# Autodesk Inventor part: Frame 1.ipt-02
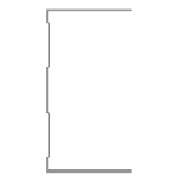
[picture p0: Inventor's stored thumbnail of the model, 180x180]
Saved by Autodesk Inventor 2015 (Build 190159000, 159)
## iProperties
IsCustomPart: 1
Created: 2015-04
Part Number: Frame 1.ipt-02
Material: Aluminum 6061
Description: Kévin Novo
Document SubType Name: Modeling
Standard: Kevin
Designer: suporte
Standards Organization: Kevin
Language: en-US
Size Designation: (Unnamed 2)
Categories: <MemberInstance><Categories><Category DisplayName="Structural Shapes" InternalName="089c4875-fa83-4c05-b084-43b9cc11f5ed" Mnemonic="GRDR"><CategoryParameter Dis
Density: 2.7 g/cm^3
Appearance: Aluminum - Flat
_CCFamilyMember: 2
_CCFamilyDisplayName: Kévin - Kévin Novo
_FrameMemberDoc: Frame Member File
_Version: 15.0.0
_GetPNFromCC: 1
G_W: 50,000 mm
G_H: 75,000 mm
G_L: 2100,000 mm
Author: suporte
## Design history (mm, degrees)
node "Start Plane"
node "End Plane"
sketch "Sketch"
  geometry: L1 (24.7, 37.5)-(24.7, 36.9); L2 (24.7, 36.9)-(-24.7, 36.9); L3 (-24.7, -36.9)-(24.7, -36.9); L4 (24.7, -36.9)-(24.7, -37.5); L5 (24.7, -37.5)-(-25.3, -37.5); L6 (-25.3, 37.5)-(24.7, 37.5); L7 (-24.7, 36.9)-(-24.7, 31.9); L8 (-24.7, 31.9)-(-23.3, 30.5); L9 (-23.3, 30.5)-(-23.3, 10.934); L10 (-23.3, 10.934)-(-24.7, 9.534); L11 (-24.7, 9.534)-(-24.7, -9.534); L12 (-24.7, -9.534)-(-23.3, -10.934); L13 (-23.3, -10.934)-(-23.3, -30.5); L14 (-23.3, -30.5)-(-24.7, -31.9); L15 (-24.7, -31.9)-(-24.7, -36.9); L16 (-25.3, -37.5)-(-25.3, -31.651); L17 (-25.3, -31.651)-(-23.9, -30.251); L18 (-23.9, -30.251)-(-23.9, -11.183); L19 (-23.9, -11.183)-(-25.3, -9.783); L20 (-25.3, -9.783)-(-25.3, 9.783); L21 (-25.3, 9.783)-(-23.9, 11.183); L22 (-23.9, 11.183)-(-23.9, 30.251); L23 (-23.9, 30.251)-(-25.3, 31.651); L24 (-25.3, 31.651)-(-25.3, 37.5); L25 (-25.3, 0)-(30.37, 0); 3 further points
  constraints: 50 end point, 10 point on line, 9 parallel, 5 perpendicular, 4 equal length, 3 midpoint, 3 vertical, 2 vertical alignment, 1 collinear, 1 horizontal, 1 horizontal alignment
  dimensions: "d3" = 0.6 distance of L1.start L1.end (= d6); "d5" = 75 distance between parallel lines of L5 L6; "d6" = 0.6 distance between parallel lines of L24 L7 (= d8); "d7" = 0.6 distance between parallel lines of L8 L23 (= d8); "d8" = 0.6 distance between parallel lines of L22 L9 (= d12); "Espessura" = 0.6 distance between parallel lines of L17 L14; "d10" = 0.6 distance between parallel lines of L13 L18 (= Espessura); "d11" = 0.6 distance between parallel lines of L12 L19 (= Espessura); "d12" = 0.6 distance between parallel lines of L21 L10 (= d11); "d13" = 5 distance of L2.end L7.end; "d15" = 135 deg angle of L9 L8; "d16" = 2 distance between parallel lines of L24 L9; "d17" = 50 distance of L6.start L1.start
extrude "Body" join sketch "Sketch" stored distance "d24" = 0.13; taper "d25" = 0 deg
node "Driven Length"
  sketch "Sketch10"
    geometry: L1 (0, 0)-(10, 0) reference
    constraints: 2 end point, 1 horizontal
  workplane "Work Plane7"
  sketch "Sketch11"
    geometry: L1 (-2, 0)-(12, 0) reference; L2 (-2, 2100)-(12, 2100) reference
    dimensions: "d27" = 2100 distance between parallel lines of L1 L2 (derived)
body "Solid1"
other parameters: "G_OFFSET_START" = 0 [user parameter; used in 1 equation term], "G_OFFSET_END" = 0 [user parameter; used in 1 equation term], "d22" = 0 (computed from G_OFFSET_START), "G_L" = 2100 (= d27) [user parameter], "d34" = 90 deg
